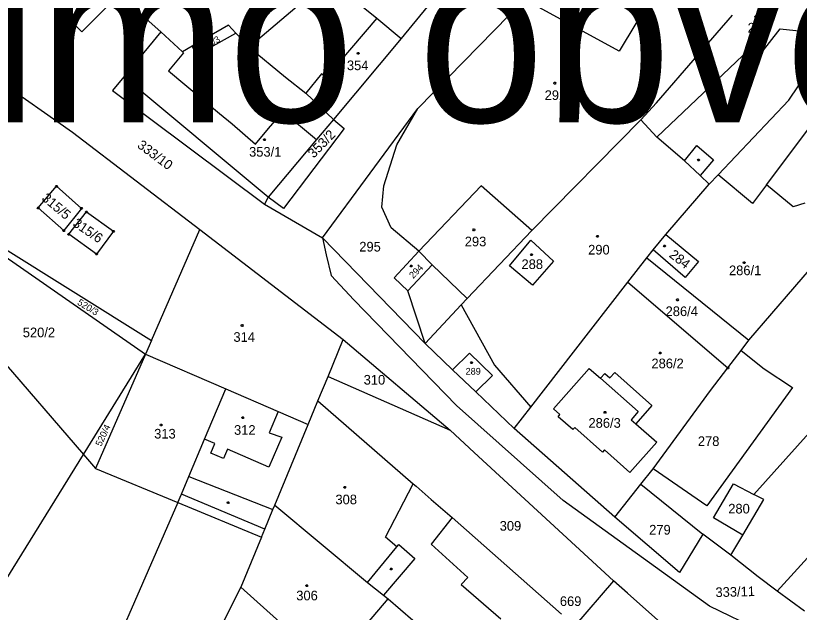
# Model space of a CAD drawing. Extents: x -634640 to -629202, y -1196156 to -1190068.
# Drawn here: x -631922.1 to -631784.1, y -1192727.8 to -1192622.8 of the extents above; entities that cross this region are included whole.
import ezdxf

# ---------------------------------------------------------------- set-up
doc = ezdxf.new("R2010")
doc.units = 0
for name, color, linetype in [('Obvod šetřený', 7, 'Continuous'), ('Vrstva 1', 7, 'Continuous'), ('Vrstva 2', 7, 'Continuous'), ('Vrstva 3', 7, 'Continuous'), ('Vrstva 4', 7, 'Continuous'), ('Vrstva 5', 7, 'Continuous'), ('Vrstva 8', 7, 'Continuous')]:
    doc.layers.add(name, color=color, linetype=linetype)

msp = doc.modelspace()

# ---------------------------------------------------------------- linework, layer by layer
at = {"layer": 'Vrstva 1'}
for p, q in [((-631801.93, -1192605.84), (-631815.78, -1192629)), ((-631841.08, -1192610.76), (-631854.21, -1192626.77)), ((-631889.18, -1192612.51), (-631899.64, -1192622.83)), ((-631866.88, -1192616.39), (-631880.98, -1192628.29)), ((-631866.88, -1192616.39), (-631858.46, -1192623.18)), ((-631910.45, -1192625.61), (-631903.97, -1192619.15)), ((-631903.97, -1192619.15), (-631899.94, -1192623.13)), ((-631851.26, -1192639.1), (-631832.48, -1192619.85)), ((-631815.78, -1192629), (-631832.48, -1192619.85)), ((-631914.61, -1192621.47), (-631910.45, -1192625.61)), ((-631899.94, -1192623.13), (-631899.64, -1192622.83)), ((-631899.64, -1192622.83), (-631896.5, -1192625.6)), ((-631858.46, -1192623.18), (-631854.21, -1192626.77)), ((-631801.97, -1192629.77), (-631795.8, -1192622.68)), ((-631939.14, -1192624.27), (-631912.1, -1192643.29)), ((-631884.59, -1192624.44), (-631891, -1192628.12)), ((-631883.29, -1192625.83), (-631884.59, -1192624.44)), ((-631896.5, -1192625.6), (-631903.03, -1192633.54)), ((-631892.72, -1192629.11), (-631896.5, -1192625.6)), ((-631880.98, -1192628.29), (-631883.29, -1192625.83)), ((-631785.88, -1192637.63), (-631778.13, -1192626.06)), ((-631854.21, -1192626.77), (-631866.12, -1192641.04)), ((-631891, -1192628.12), (-631892.72, -1192629.11)), ((-631880.98, -1192628.29), (-631874.57, -1192633.59)), ((-631809.23, -1192638.11), (-631801.97, -1192629.77)), ((-631903.03, -1192633.54), (-631905.05, -1192635.93)), ((-631874.57, -1192633.59), (-631870.97, -1192636.43)), ((-631905.05, -1192635.93), (-631878.24, -1192655.99)), ((-631870.97, -1192636.43), (-631866.12, -1192641.04)), ((-631812, -1192641.1), (-631809.23, -1192638.11)), ((-631798.33, -1192650.8), (-631785.88, -1192637.63)), ((-631868.04, -1192661.91), (-631851.26, -1192639.1)), ((-631854.97, -1192645.49), (-631851.26, -1192639.1)), ((-631866.12, -1192641.04), (-631869.09, -1192644.58)), ((-631866.12, -1192641.04), (-631864.21, -1192642.63)), ((-631831.2, -1192660.61), (-631812, -1192641.1)), ((-631809.18, -1192644.16), (-631812, -1192641.1)), ((-631864.21, -1192642.63), (-631874.89, -1192656.75)), ((-631912.1, -1192643.29), (-631889.67, -1192660.43)), ((-631804.3, -1192648.34), (-631809.18, -1192644.16)), ((-631869.09, -1192644.58), (-631877.63, -1192654.75)), ((-631857.24, -1192652.73), (-631854.97, -1192645.49)), ((-631801.52, -1192650.94), (-631804.3, -1192648.34)), ((-631799.92, -1192652.43), (-631801.52, -1192650.94)), ((-631799.92, -1192652.43), (-631798.33, -1192650.8)), ((-631792.32, -1192655.84), (-631798.33, -1192650.8)), ((-631943.37, -1192651.7), (-631899.23, -1192682.4)), ((-631943.37, -1192651.7), (-631898.18, -1192679.98)), ((-631807.54, -1192661.31), (-631799.92, -1192652.43)), ((-631789.83, -1192652.53), (-631792.32, -1192655.84)), ((-631785.16, -1192656.42), (-631789.83, -1192652.53)), ((-631857.6, -1192656.47), (-631857.24, -1192652.73)), ((-631840.11, -1192652.74), (-631851.1, -1192664.25)), ((-631831.2, -1192660.61), (-631840.11, -1192652.74)), ((-631877.63, -1192654.75), (-631878.24, -1192655.99)), ((-631874.89, -1192656.75), (-631877.63, -1192654.75)), ((-631878.24, -1192655.99), (-631868.04, -1192661.91)), ((-631855.95, -1192660.11), (-631857.6, -1192656.47)), ((-631783.11, -1192655.81), (-631785.16, -1192656.42)), ((-631898.18, -1192679.98), (-631889.67, -1192660.43)), ((-631889.67, -1192660.43), (-631864.39, -1192679.82)), ((-631851.1, -1192664.25), (-631855.95, -1192660.11)), ((-631842.58, -1192672.59), (-631831.2, -1192660.61)), ((-631943.25, -1192661.82), (-631910.15, -1192700.05)), ((-631868.04, -1192661.91), (-631867.41, -1192664.87)), ((-631849.97, -1192680.51), (-631868.04, -1192661.91)), ((-631809.82, -1192664.02), (-631807.54, -1192661.31)), ((-631807.54, -1192661.31), (-631801.81, -1192666.07)), ((-631792.92, -1192679.94), (-631777.31, -1192661.71)), ((-631835.13, -1192666.85), (-631831.32, -1192662.32)), ((-631831.32, -1192662.32), (-631827.37, -1192666.02)), ((-631867.41, -1192664.87), (-631866.51, -1192668.55)), ((-631855.43, -1192668.94), (-631851.1, -1192664.25)), ((-631848.75, -1192666.62), (-631851.1, -1192664.25)), ((-631810.9, -1192665.41), (-631809.82, -1192664.02)), ((-631804.16, -1192668.86), (-631809.82, -1192664.02)), ((-631827.37, -1192666.02), (-631831.05, -1192670.2)), ((-631814.26, -1192669.72), (-631810.9, -1192665.41)), ((-631810.9, -1192665.41), (-631792.92, -1192679.94)), ((-631801.81, -1192666.07), (-631804.16, -1192668.86)), ((-631842.58, -1192672.59), (-631848.75, -1192666.62)), ((-631831.05, -1192670.2), (-631835.13, -1192666.85)), ((-631862.51, -1192672.83), (-631866.51, -1192668.55)), ((-631853.04, -1192671.22), (-631855.43, -1192668.94)), ((-631823.81, -1192682), (-631814.26, -1192669.72)), ((-631814.26, -1192669.72), (-631796.64, -1192684.79)), ((-631849.97, -1192680.51), (-631853.04, -1192671.22)), ((-631844.44, -1192691.44), (-631862.51, -1192672.83)), ((-631843.6, -1192673.69), (-631842.58, -1192672.59)), ((-631849.97, -1192680.51), (-631843.6, -1192673.69)), ((-631843.6, -1192673.69), (-631837.76, -1192684.34)), ((-631898.18, -1192679.98), (-631899.23, -1192682.4)), ((-631867.07, -1192686.31), (-631864.39, -1192679.82)), ((-631864.39, -1192679.82), (-631845.57, -1192695.78)), ((-631794.31, -1192681.75), (-631792.92, -1192679.94)), ((-631845.13, -1192685.12), (-631849.97, -1192680.51)), ((-631910.15, -1192700.05), (-631899.23, -1192682.4)), ((-631899.23, -1192682.4), (-631908, -1192702.53)), ((-631899.23, -1192682.4), (-631885.06, -1192688.5)), ((-631831.36, -1192691.7), (-631823.81, -1192682)), ((-631796.64, -1192684.79), (-631794.31, -1192681.75)), ((-631794.31, -1192681.75), (-631790.22, -1192684.94)), ((-631837.76, -1192684.34), (-631831.36, -1192691.7)), ((-631841.03, -1192689.02), (-631845.13, -1192685.12)), ((-631827.34, -1192692.03), (-631821.07, -1192684.89)), ((-631821.07, -1192684.89), (-631819.09, -1192686.63)), ((-631817.43, -1192686.57), (-631816.56, -1192685.6)), ((-631816.56, -1192685.6), (-631810.01, -1192691.44)), ((-631799.7, -1192688.78), (-631796.64, -1192684.79)), ((-631790.22, -1192684.94), (-631785.27, -1192688.23)), ((-631868.85, -1192690.58), (-631867.07, -1192686.31)), ((-631867.07, -1192686.31), (-631845.57, -1192695.78)), ((-631819.09, -1192686.63), (-631818.32, -1192685.77)), ((-631818.32, -1192685.77), (-631817.43, -1192686.57)), ((-631792.06, -1192707.08), (-631773.62, -1192686.44)), ((-631888.83, -1192697.36), (-631885.06, -1192688.5)), ((-631885.06, -1192688.5), (-631875.84, -1192692.46)), ((-631785.27, -1192688.23), (-631800.36, -1192709.1)), ((-631834.27, -1192695.45), (-631841.03, -1192689.02)), ((-631809.8, -1192702.55), (-631799.7, -1192688.78)), ((-631870.58, -1192694.79), (-631868.85, -1192690.58)), ((-631868.85, -1192690.58), (-631852.05, -1192705.21)), ((-631875.84, -1192692.46), (-631870.58, -1192694.79)), ((-631825.63, -1192708.13), (-631844.44, -1192691.44)), ((-631834.27, -1192695.45), (-631831.36, -1192691.7)), ((-631826.21, -1192693.03), (-631827.34, -1192692.03)), ((-631810.01, -1192691.44), (-631812.87, -1192694.65)), ((-631826.54, -1192693.41), (-631826.21, -1192693.03)), ((-631823.94, -1192695.65), (-631826.54, -1192693.41)), ((-631787.93, -1192724.11), (-631760.2, -1192693.47)), ((-631876.46, -1192708.97), (-631870.58, -1192694.79)), ((-631823.61, -1192695.28), (-631823.94, -1192695.65)), ((-631818.71, -1192699.62), (-631823.61, -1192695.28)), ((-631812.87, -1192694.65), (-631809.18, -1192697.85)), ((-631845.57, -1192695.78), (-631841.3, -1192699.71)), ((-631816.56, -1192711.07), (-631834.27, -1192695.45)), ((-631891.56, -1192703.9), (-631888.83, -1192697.36)), ((-631809.18, -1192697.85), (-631813.89, -1192703.22)), ((-631818.38, -1192699.25), (-631818.71, -1192699.62)), ((-631813.89, -1192703.22), (-631818.38, -1192699.25)), ((-632001.69, -1192847.96), (-631910.15, -1192700.05)), ((-631910.15, -1192700.05), (-631908, -1192702.53)), ((-631841.3, -1192699.71), (-631816.78, -1192722.29)), ((-631908, -1192702.53), (-631893.53, -1192708.5)), ((-631811.97, -1192705.29), (-631809.8, -1192702.55)), ((-631800.36, -1192709.1), (-631809.8, -1192702.55)), ((-631892.85, -1192707.01), (-631891.56, -1192703.9)), ((-631856.97, -1192714.6), (-631852.05, -1192705.21)), ((-631852.05, -1192705.21), (-631851.57, -1192705.62)), ((-631851.57, -1192705.62), (-631848.88, -1192707.95)), ((-631816.56, -1192711.07), (-631811.97, -1192705.29)), ((-631811.97, -1192705.29), (-631801.07, -1192714.08)), ((-631799.2, -1192711.22), (-631795.64, -1192705.23)), ((-631795.64, -1192705.23), (-631792.06, -1192707.08)), ((-631893.53, -1192708.5), (-631892.85, -1192707.01)), ((-631790.33, -1192707.97), (-631792.06, -1192707.08)), ((-631893.53, -1192708.5), (-631878.78, -1192714.59)), ((-631876.79, -1192709.76), (-631876.46, -1192708.97)), ((-631876.46, -1192708.97), (-631860.13, -1192722.62)), ((-631848.88, -1192707.95), (-631845.21, -1192711.13)), ((-631799.89, -1192726.74), (-631825.63, -1192708.13)), ((-631794, -1192714.25), (-631790.33, -1192707.97)), ((-631878.2, -1192713.18), (-631876.79, -1192709.76)), ((-631845.21, -1192711.13), (-631825.94, -1192728.19)), ((-631805.18, -1192720.86), (-631816.56, -1192711.07)), ((-631794, -1192714.25), (-631799.2, -1192711.22)), ((-631878.78, -1192714.59), (-631878.2, -1192713.18)), ((-631878.78, -1192714.59), (-631882.43, -1192723.39)), ((-631854.96, -1192716.33), (-631856.97, -1192714.6)), ((-631801.07, -1192714.08), (-631805.18, -1192720.86)), ((-631796.13, -1192717.78), (-631801.07, -1192714.08)), ((-631796.13, -1192717.78), (-631794, -1192714.25)), ((-631860.13, -1192722.62), (-631854.96, -1192716.33)), ((-631791.3, -1192721.62), (-631796.13, -1192717.78)), ((-631787.93, -1192724.11), (-631791.3, -1192721.62)), ((-631860.13, -1192722.62), (-631857.28, -1192724.84)), ((-631816.78, -1192722.29), (-631823.63, -1192730.27)), ((-631814.33, -1192724.46), (-631816.78, -1192722.29)), ((-631882.43, -1192723.39), (-631885.53, -1192729.56)), ((-631882.43, -1192723.39), (-631866.57, -1192737.61)), ((-631783.13, -1192727.65), (-631787.93, -1192724.11)), ((-631860.1, -1192729.75), (-631856.45, -1192725.49)), ((-631857.28, -1192724.84), (-631856.45, -1192725.49)), ((-631856.45, -1192725.49), (-631845.36, -1192735.03)), ((-631804.93, -1192732.81), (-631814.33, -1192724.46)), ((-631782.1, -1192735.29), (-631799.89, -1192726.74))]:
    msp.add_line(p, q, dxfattribs=at)
for points in [[(-631891, -1192628.12), (-631890.21, -1192629.74), (-631883.29, -1192625.83)], [(-631913.61, -1192660.62), (-631918.11, -1192656.62), (-631914.89, -1192652.81), (-631910.5, -1192656.7), (-631913.61, -1192660.62)], [(-631904.87, -1192660.73), (-631907.84, -1192664.75), (-631912.73, -1192661.26), (-631909.63, -1192657.33), (-631904.87, -1192660.73)], [(-631893.53, -1192708.5), (-631911.2, -1192749.01), (-631899.23, -1192758.66)]]:
    msp.add_lwpolyline(points, dxfattribs=at)
at = {"layer": 'Vrstva 3'}
for points in [[(-631827.04, -1192634.5), (-631826.95, -1192634.65), (-631827.04, -1192634.8), (-631827.22, -1192634.8), (-631827.31, -1192634.65), (-631827.22, -1192634.5), (-631827.04, -1192634.5)], [(-631819.53, -1192661.48), (-631819.44, -1192661.63), (-631819.53, -1192661.78), (-631819.71, -1192661.78), (-631819.8, -1192661.63), (-631819.71, -1192661.48), (-631819.53, -1192661.48)], [(-631793.68, -1192666.12), (-631793.59, -1192666.27), (-631793.68, -1192666.42), (-631793.86, -1192666.42), (-631793.95, -1192666.27), (-631793.86, -1192666.12), (-631793.68, -1192666.12)], [(-631805.44, -1192672.66), (-631805.35, -1192672.81), (-631805.44, -1192672.96), (-631805.62, -1192672.96), (-631805.71, -1192672.81), (-631805.62, -1192672.66), (-631805.44, -1192672.66)], [(-631882.11, -1192677.18), (-631882.02, -1192677.33), (-631882.11, -1192677.48), (-631882.29, -1192677.48), (-631882.38, -1192677.33), (-631882.29, -1192677.18), (-631882.11, -1192677.18)], [(-631808.47, -1192682.02), (-631808.38, -1192682.17), (-631808.47, -1192682.32), (-631808.65, -1192682.32), (-631808.74, -1192682.17), (-631808.65, -1192682.02), (-631808.47, -1192682.02)], [(-631896.37, -1192694.68), (-631896.28, -1192694.83), (-631896.37, -1192694.98), (-631896.55, -1192694.98), (-631896.64, -1192694.83), (-631896.55, -1192694.68), (-631896.37, -1192694.68)], [(-631864.03, -1192705.69), (-631863.94, -1192705.84), (-631864.03, -1192705.99), (-631864.21, -1192705.99), (-631864.3, -1192705.84), (-631864.21, -1192705.69), (-631864.03, -1192705.69)], [(-631870.73, -1192722.98), (-631870.64, -1192723.13), (-631870.73, -1192723.28), (-631870.91, -1192723.28), (-631871, -1192723.13), (-631870.91, -1192722.98), (-631870.73, -1192722.98)]]:
    msp.add_lwpolyline(points, dxfattribs=at)
at = {"layer": 'Vrstva 4'}
for p, q in [((-631858.46, -1192623.18), (-631867.39, -1192633.63)), ((-631792.22, -1192631.23), (-631787.42, -1192625.1)), ((-631787.42, -1192625.1), (-631782.46, -1192625.6)), ((-631892.72, -1192629.11), (-631892.51, -1192629.31)), ((-631892.51, -1192629.31), (-631895.14, -1192632.5)), ((-631809.18, -1192644.16), (-631794.03, -1192629.77)), ((-631794.03, -1192629.77), (-631792.22, -1192631.23)), ((-631895.14, -1192632.5), (-631886.21, -1192640)), ((-631868.19, -1192633.03), (-631870.97, -1192636.43)), ((-631867.39, -1192633.63), (-631868.19, -1192633.03)), ((-631877.63, -1192654.75), (-631903.03, -1192633.54)), ((-631789.83, -1192652.53), (-631778.83, -1192637.89)), ((-631877.53, -1192642.61), (-631875.15, -1192639.87)), ((-631804.3, -1192648.34), (-631802.12, -1192645.64)), ((-631802.12, -1192645.64), (-631799.2, -1192648.14)), ((-631799.2, -1192648.14), (-631801.52, -1192650.94)), ((-631853.04, -1192671.22), (-631848.75, -1192666.62)), ((-631845.13, -1192685.12), (-631842.14, -1192682.18)), ((-631842.14, -1192682.18), (-631838.08, -1192686.11)), ((-631838.08, -1192686.11), (-631841.03, -1192689.02)), ((-631819.09, -1192686.63), (-631812.44, -1192692.47)), ((-631875.84, -1192692.46), (-631877.42, -1192696.25)), ((-631812.44, -1192692.47), (-631813.7, -1192693.93)), ((-631813.7, -1192693.93), (-631812.87, -1192694.65)), ((-631877.42, -1192696.25), (-631875.2, -1192696.98)), ((-631887.02, -1192698.14), (-631888.83, -1192697.36)), ((-631887.73, -1192699.79), (-631887.02, -1192698.14)), ((-631875.2, -1192696.98), (-631877.47, -1192702.26)), ((-631884.76, -1192699.11), (-631885.47, -1192700.76)), ((-631877.47, -1192702.26), (-631884.76, -1192699.11)), ((-631885.47, -1192700.76), (-631887.73, -1192699.79)), ((-631891.56, -1192703.9), (-631876.79, -1192709.76)), ((-631878.2, -1192713.18), (-631892.85, -1192707.01)), ((-631845.21, -1192711.13), (-631848.92, -1192715.87)), ((-631854.96, -1192716.33), (-631854.6, -1192715.9)), ((-631854.6, -1192715.9), (-631851.77, -1192718.39)), ((-631848.92, -1192715.87), (-631842.45, -1192721.69)), ((-631851.77, -1192718.39), (-631857.28, -1192724.84)), ((-631842.45, -1192721.69), (-631843.6, -1192722.93)), ((-631843.6, -1192722.93), (-631836.65, -1192729.01))]:
    msp.add_line(p, q, dxfattribs=at)
for points in [[(-631886.21, -1192640), (-631883.96, -1192641.81), (-631879.85, -1192645.37), (-631877.53, -1192642.61)], [(-631875.15, -1192639.87), (-631875, -1192639.62), (-631869.09, -1192644.58)]]:
    msp.add_lwpolyline(points, dxfattribs=at)
at = {"layer": 'Vrstva 5'}
for points in [[(-631791.63, -1192622.77), (-631791.54, -1192622.92), (-631791.63, -1192623.07), (-631791.81, -1192623.07), (-631791.9, -1192622.92), (-631791.81, -1192622.77), (-631791.63, -1192622.77)], [(-631887.7, -1192626.42), (-631887.61, -1192626.57), (-631887.7, -1192626.72), (-631887.88, -1192626.72), (-631887.97, -1192626.57), (-631887.88, -1192626.42), (-631887.7, -1192626.42)], [(-631861.67, -1192629.25), (-631861.58, -1192629.4), (-631861.67, -1192629.55), (-631861.85, -1192629.55), (-631861.94, -1192629.4), (-631861.85, -1192629.25), (-631861.67, -1192629.25)], [(-631878.19, -1192644.43), (-631878.1, -1192644.58), (-631878.19, -1192644.73), (-631878.37, -1192644.73), (-631878.46, -1192644.58), (-631878.37, -1192644.43), (-631878.19, -1192644.43)], [(-631801.72, -1192648.05), (-631801.63, -1192648.2), (-631801.72, -1192648.35), (-631801.9, -1192648.35), (-631801.99, -1192648.2), (-631801.9, -1192648.05), (-631801.72, -1192648.05)], [(-631841.28, -1192660.33), (-631841.19, -1192660.48), (-631841.28, -1192660.63), (-631841.46, -1192660.63), (-631841.55, -1192660.48), (-631841.46, -1192660.33), (-631841.28, -1192660.33)], [(-631807.7, -1192663.16), (-631807.61, -1192663.31), (-631807.7, -1192663.46), (-631807.88, -1192663.46), (-631807.97, -1192663.31), (-631807.88, -1192663.16), (-631807.7, -1192663.16)], [(-631831.12, -1192664.69), (-631831.03, -1192664.84), (-631831.12, -1192664.99), (-631831.3, -1192664.99), (-631831.39, -1192664.84), (-631831.3, -1192664.69), (-631831.12, -1192664.69)], [(-631852.33, -1192666.68), (-631852.24, -1192666.83), (-631852.33, -1192666.98), (-631852.51, -1192666.98), (-631852.6, -1192666.83), (-631852.51, -1192666.68), (-631852.33, -1192666.68)], [(-631841.7, -1192683.73), (-631841.61, -1192683.88), (-631841.7, -1192684.03), (-631841.88, -1192684.03), (-631841.97, -1192683.88), (-631841.88, -1192683.73), (-631841.7, -1192683.73)], [(-631818.19, -1192692.47), (-631818.1, -1192692.62), (-631818.19, -1192692.77), (-631818.37, -1192692.77), (-631818.46, -1192692.62), (-631818.37, -1192692.47), (-631818.19, -1192692.47)], [(-631881.99, -1192693.4), (-631881.9, -1192693.55), (-631881.99, -1192693.7), (-631882.17, -1192693.7), (-631882.26, -1192693.55), (-631882.17, -1192693.4), (-631881.99, -1192693.4)], [(-631884.57, -1192708.37), (-631884.48, -1192708.52), (-631884.57, -1192708.67), (-631884.75, -1192708.67), (-631884.84, -1192708.52), (-631884.75, -1192708.37), (-631884.57, -1192708.37)], [(-631855.85, -1192720.05), (-631855.76, -1192720.2), (-631855.85, -1192720.35), (-631856.03, -1192720.35), (-631856.12, -1192720.2), (-631856.03, -1192720.05), (-631855.85, -1192720.05)]]:
    msp.add_lwpolyline(points, dxfattribs=at)
at = {"layer": 'Vrstva 8'}
for points in [[(-631914.8, -1192652.66), (-631914.71, -1192652.81), (-631914.8, -1192652.96), (-631914.98, -1192652.96), (-631915.07, -1192652.81), (-631914.98, -1192652.66), (-631914.8, -1192652.66)], [(-631918.02, -1192656.47), (-631917.93, -1192656.62), (-631918.02, -1192656.77), (-631918.2, -1192656.77), (-631918.29, -1192656.62), (-631918.2, -1192656.47), (-631918.02, -1192656.47)], [(-631910.41, -1192656.55), (-631910.32, -1192656.7), (-631910.41, -1192656.85), (-631910.59, -1192656.85), (-631910.68, -1192656.7), (-631910.59, -1192656.55), (-631910.41, -1192656.55)], [(-631909.54, -1192657.18), (-631909.45, -1192657.33), (-631909.54, -1192657.48), (-631909.72, -1192657.48), (-631909.81, -1192657.33), (-631909.72, -1192657.18), (-631909.54, -1192657.18)], [(-631913.52, -1192660.47), (-631913.43, -1192660.62), (-631913.52, -1192660.77), (-631913.7, -1192660.77), (-631913.79, -1192660.62), (-631913.7, -1192660.47), (-631913.52, -1192660.47)], [(-631904.78, -1192660.58), (-631904.69, -1192660.73), (-631904.78, -1192660.88), (-631904.96, -1192660.88), (-631905.05, -1192660.73), (-631904.96, -1192660.58), (-631904.78, -1192660.58)], [(-631912.64, -1192661.11), (-631912.55, -1192661.26), (-631912.64, -1192661.41), (-631912.82, -1192661.41), (-631912.91, -1192661.26), (-631912.82, -1192661.11), (-631912.64, -1192661.11)], [(-631907.75, -1192664.6), (-631907.66, -1192664.75), (-631907.75, -1192664.9), (-631907.93, -1192664.9), (-631908.02, -1192664.75), (-631907.93, -1192664.6), (-631907.75, -1192664.6)], [(-631796.55, -1192684.64), (-631796.46, -1192684.79), (-631796.55, -1192684.94), (-631796.73, -1192684.94), (-631796.82, -1192684.79), (-631796.73, -1192684.64), (-631796.55, -1192684.64)]]:
    msp.add_lwpolyline(points, dxfattribs=at)

# ---------------------------------------------------------------- texts
at = {"layer": 'Obvod šetřený'}
msp.add_text('mimo obvod KoPÚ', height=30, dxfattribs=at).set_placement((-631960.455, -1192641.53))
at = {"layer": 'Vrstva 2'}
for s, height, p in [('287', 1.7, (-631793.153, -1192625.73)), ('354', 1.7, (-631863.743, -1192632.36)), ('292', 1.7, (-631828.913, -1192637.61)), ('353/1', 1.7, (-631880.973, -1192647.6)), ('293', 1.7, (-631842.983, -1192663.39)), ('295', 1.7, (-631861.563, -1192664.3)), ('290', 1.7, (-631821.253, -1192664.83)), ('288', 1.7, (-631832.993, -1192667.38)), ('286/1', 1.7, (-631796.443, -1192668.47)), ('286/4', 1.7, (-631807.609, -1192675.67)), ('520/2', 1.7, (-631920.833, -1192679.4)), ('314', 1.7, (-631883.733, -1192680.21)), ('286/2', 1.7, (-631810.103, -1192684.86)), ('289', 1.2, (-631842.842, -1192686)), ('310', 1.7, (-631860.793, -1192687.74)), ('286/3', 1.7, (-631821.193, -1192695.34)), ('312', 1.7, (-631883.623, -1192696.58)), ('313', 1.7, (-631897.693, -1192697.24)), ('278', 1.7, (-631801.923, -1192698.55)), ('308', 1.7, (-631865.763, -1192708.82)), ('280', 1.7, (-631796.573, -1192710.44)), ('309', 1.7, (-631836.833, -1192713.47)), ('279', 1.7, (-631810.503, -1192714.15)), ('306', 1.7, (-631872.663, -1192725.73))]:
    msp.add_text(s, height=height, dxfattribs=at).set_placement(p)
for s, height, rotation, p in [('353/3', 1.14, 30.99702, (-631889.227, -1192629.2)), ('353/2', 1.7, 45.95121, (-631869.585, -1192647.959)), ('333/10', 1.7, 323.20549, (-631900.8, -1192645.872)), ('315/5', 1.7, 319.76774, (-631917.633, -1192655.123)), ('315/6', 1.7, 325.72651, (-631912.173, -1192659.699)), ('284', 1.7, 322.23146, (-631807.122, -1192665.145)), ('294', 1.2, 46.06581, (-631852.054, -1192669.159)), ('520/3', 1.19, 328.30482, (-631911.339, -1192673.567)), ('520/4', 1.19, 64.97341, (-631907.03, -1192698.719)), ('333/11', 1.7, 1.54699, (-631798.803, -1192725.164))]:
    msp.add_text(s, height=height, rotation=rotation, dxfattribs=at).set_placement(p)
at = {"layer": 'Vrstva 8'}
msp.add_text('669', height=1.7, dxfattribs=at).set_placement((-631826.233, -1192726.73))

doc.saveas('drawing.dxf')
